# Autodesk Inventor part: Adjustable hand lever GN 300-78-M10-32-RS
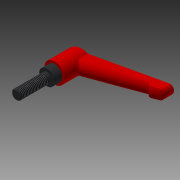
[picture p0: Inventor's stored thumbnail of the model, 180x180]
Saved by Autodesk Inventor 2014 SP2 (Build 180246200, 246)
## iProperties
Created: 2019-10
Part Number: Adjustable hand lever GN 300-78-M10-32-RS
Material: Generic
Catalog Web Link: www.cadenas.de
Description: GN 300-Adjustable hand levers with male thread
Vendor: GANTER
Document SubType Name: Modeling
Designer: psadmin
Manufacturer: GANTER
Mass: 144.5 g
Surface Area: 68.1489 cm^2
Volume: 21.9822 cm^3
Density: 1 g/cm^3
Appearance: PSOLRGB-255-0-0
Category: PARTsolutions
Company: GANTER
Title: Adjustable hand lever GN 300-78-M10-32-RS
Author: Cadenas PARTsolutions
Comments: Adjustable hand levers with male thread
PSOL_IDENT_0: {$CADENAS_DATA\23d-libs\ganter\data\2_1\gn_300\gn_300_ms\gn300_ms.prj},226 {VTYP=3D},{NB=Adjustable
PSOL_IDENT_1: hand lever GN 300-78-M10-32-RS},{LINA=Adjustable hand lever GN 300-78-M10-32-RS},{NN=GN 300},{DATE=0
PSOL_IDENT_2: 8.10.2019 15:17:01},{GEOMDATE=24.09.2019 13:55:25},{VERSION=v1},{LINEID=5900},{WBVAR=},{WBNUMERIC=}
PSOL_IDENT_3: {NB=Verstellbarer Klemmhebel GN 300-78-M10-32-RS},{LINA=Verstellbarer Klemmhebel GN 300-78-M10-32-R
PSOL_IDENT_4: S},{KT=DUMMY},{PARTNUMBER=GN 300-78-M10-32-RS},{NORMNR=GN 300},{L1=78},{L=13.000},{D1=M10},{D1Y=10},
PSOL_IDENT_5: {D1X=8,10},{L2=32},{L2X=16,20,25,32,40,50,63,80},{FARBE=rot (strukturmatt)},{VER=4},{AUSWAHL= 'SW', '
PSOL_IDENT_6: schwarz (strukturmatt)', 'SZ', 'schwarz (seidenglanz)', 'OR'  , 'orange', 'RS', 'rot (strukturmatt)'
PSOL_IDENT_7: , 'SB', 'silber', 'CR', 'verchromt', 'RH'  , 'unlackiert'},{D3=16.0},{D4=21.0},{H1=36.0},{H2=8.0},{H
PSOL_IDENT_8: 3=54},{H4=4.0},{T=14},{ABS1=3.000},{R1=4.000},{R2=6.000},{R3=3.000},{ABS2=15.000},{R4=3.000},{R5=3.0
PSOL_IDENT_9: 00},{R6=6.000},{ABS3=22.000},{ABS4=14.000},{ABS5=6.500},{SW=5.000},{VERS=2},{FARBER=1},{FARBEG=0},{F
PSOL_IDENT_10: ARBEB=0},{FARBEX=RS},{WEIGHT=0.1445},{CTN=84879090},{ROHS=YES},{INFOGANTER=Produktdetails},{INFOGANT
PSOL_IDENT_11: ERX=https://www.ganternorm.com/en/products/2.1-Tensioning-clamping-switching-with-levers/GN-300-Adju
PSOL_IDENT_12: stable-hand-levers-Zinc-die-casting-with-threaded-stud},{TT=25.000},{AA=4.430},{LL=2.000},{DIST=5.28
PSOL_IDENT_13: }
NN: GN 300
NT: Adjustable hand levers with male thread
NB: Adjustable hand lever GN 300-78-M10-32-RS
NBSYN: Adjustable hand lever $PARTNUMBER.
LINA: Adjustable hand lever GN 300-78-M10-32-RS
PARTNUMBER: GN 300-78-M10-32-RS
L1: 78
D1: M10
L2: 32
FARBE: red (textured finish)
D3: 16
D4: 21
H1: 36
H2: 8
H3: 54
H4: 4
WEIGHT: 0.1445
CTN: 84879090
ROHS: YES
INFOGANTER: Product details
SUPPLIER: GANTER
ARTICLENO: Adjustable hand lever GN 300-78-M10-32-RS
BOMINFO: Adjustable hand lever GN 300-78-M10-32-RS
CREATOR: CADENAS GmbH
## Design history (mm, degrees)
sketch "Sketch_1"
  geometry: L1 (0, 18.178)-(0, 33.1); L2 (0, 33.1)-(79, 54.268); L3 (79, 54.268)-(79, 43.739); L4 (79, 43.739)-(67.844, 39.679); L5 (63.999, 41.472)-(0, 18.178); L6 (0, 18.178)-(0, 33.1); A1 r 3 centre (66.818, 42.498) between (63.999, 41.472) and (67.844, 39.679)
  constraints: 12 end point, 2 point on circle, 1 centre point
sketch "Sketch_2"
  geometry: L1 (156, 156)-(-156, 156); L2 (-156, 156)-(-156, -156); L3 (-156, -156)-(156, -156); L4 (156, -156)-(156, 156); L5 (-7.348, -7.5)-(-7.348, 7.5); L6 (-7.348, 7.5)-(-75.107, 5.134); L7 (-75.107, -5.134)-(-7.348, -7.5); A1 r 6.001 centre (-72, 0) between (-75.107, 5.134) and (-75.107, -5.134)
  constraints: 14 end point, 2 point on circle, 1 centre point
revolve "Revolution1" stored, may be unused: angle "d0" = 360 deg
extrude "Extrusion1" cut sketch "Sketch_2" distance "d1" = 58; taper "d2" = 0 deg
sketch "Sketch_3"
  geometry: L1 (-11.5, 30.019)-(78, 54); L2 (78, 54)-(78, 58); L3 (78, 58)-(-11.5, 58); L4 (-11.5, 58)-(-11.5, 30.019)
  constraints: 8 end point
sketch "Sketch_15"
  geometry: L1 (-2.839, 25.978)-(61.16, 49.271); L2 (0, 18.178)-(0, 7.537); L3 (0, 7.537)-(79, 36.29); L4 (79, 36.29)-(79, 47.576); L5 (79, 47.576)-(77.999, 47.576); L6 (74.051, 41.938)-(67.844, 39.679); L7 (63.999, 41.472)-(0, 18.178); A1 r 6 centre (71.999, 47.576) between (74.051, 41.938) and (77.999, 47.576); A2 r 3 centre (66.818, 42.498) between (63.999, 41.472) and (67.844, 39.679)
  constraints: 14 end point, 4 point on circle, 2 centre point
revolve "Revolution2" sketch "Sketch_15" stored, may be unused: angle "d3" = 180 deg
sketch "Sketch_20"
  geometry: L1 (0, 0)-(0, 33.1); L2 (0, 33.1)-(10.5, 35.913); L3 (10.5, 35.913)-(10.5, 8); L4 (10.5, 8)-(8, 8); L5 (8, 8)-(8, 0); L6 (8, 0)-(0, 0); L7 (0, 0)-(0, 33.1)
  constraints: 14 end point
revolve "Revolution3" sketch "Sketch_20" stored, may be unused: angle "d4" = 360 deg
extrude "Extrusion2" cut sketch "Sketch_3" stored distance "d5" = 23; taper "d6" = 0 deg
sketch "Sketch_4"
  geometry: L1 (0, 20.153)-(0, 36); L2 (0, 36)-(5, 36); L3 (6.5, 34.5)-(6.5, 20.153); L4 (6.5, 20.153)-(0, 20.153); L5 (0, 20.153)-(0, 36); A1 r 1.5 centre (5, 34.5) between (6.5, 34.5) and (5, 36)
  constraints: 10 end point, 2 point on circle, 1 centre point
revolve "Revolution4" sketch "Sketch_4" stored, may be unused: angle "d7" = 360 deg
sketch "Sketch7"
  geometry: 1 further point
hole "Hole1" sketch "Sketch7" at (0, 0) diameter "d8" = 4.43; stored, may be unused: countersink angle "d12" = 90 deg, drill point angle "d14" = 120 deg; dims "d9" = 6, "d10" = 4, "d11" = 2, "d13" = 2
sketch "Sketch_10"
  geometry: C1 r 2.658 at (0, 0); A1 r 0.443 centre (-1.535, -0.886) between (-1.839, -0.564) and (-1.408, -1.31); A2 r 0.775 centre (-1.185, -2.053) between (-0.431, -1.874) and (-1.408, -1.31); A3 r 0.443 centre (0, -1.772) between (-0.431, -1.874) and (0.431, -1.874); A4 r 0.775 centre (1.185, -2.053) between (1.408, -1.31) and (0.431, -1.874); A5 r 0.443 centre (1.535, -0.886) between (1.408, -1.31) and (1.839, -0.564); A6 r 0.775 centre (2.371, 0) between (1.839, 0.564) and (1.839, -0.564); A7 r 0.443 centre (1.535, 0.886) between (1.839, 0.564) and (1.408, 1.31); A8 r 0.775 centre (1.185, 2.053) between (0.431, 1.874) and (1.408, 1.31); A9 r 0.443 centre (0, 1.772) between (0.431, 1.874) and (-0.431, 1.874); A10 r 0.775 centre (-1.185, 2.053) between (-1.408, 1.31) and (-0.431, 1.874); A11 r 0.443 centre (-1.535, 0.886) between (-1.408, 1.31) and (-1.839, 0.564); A12 r 0.775 centre (-2.371, 0) between (-1.839, -0.564) and (-1.839, 0.564); 1 further point
  constraints: 24 point on circle, 13 centre point
extrude "Extrusion3" join sketch "Sketch_10" distance "d15" = 4; taper "d16" = 0 deg
sketch "Sketch_11"
  geometry: L1 (0, 34.721)-(0, 36); L2 (0, 36)-(2.215, 36); L3 (2.215, 36)-(0, 34.721); L4 (0, 34.721)-(0, 36)
  constraints: 8 end point
revolve "Revolution5" sketch "Sketch_11" stored, may be unused: angle "d17" = 360 deg
sketch "Sketch_6"
  geometry: L1 (0, -32)-(0, 0); L2 (0, 0)-(5, 0); L3 (5, 0)-(5, -31.08); L4 (5, -31.08)-(4.08, -32); L5 (4.08, -32)-(0, -32); L6 (0, -32)-(0, 0)
  constraints: 12 end point
revolve "Revolution6" sketch "Sketch_6" stored, may be unused: angle "d18" = 360 deg
thread "Thread1" dims "d19" = 27.88, "d20" = 0
node "T_XY"
node "T_YZ"
node "T_ZX"
node "T_X"
node "T_Y"
node "T_Z"
node "T_Center"
body "Solid1"
other parameters: "d21" = 0
